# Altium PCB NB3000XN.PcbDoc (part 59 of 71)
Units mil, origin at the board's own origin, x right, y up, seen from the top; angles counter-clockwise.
Board outline 9527.56 x 6929.77 mil, 6 copper layers (Top Layer, GND+SHIELD, MidLayer1, MidLayer2, P2 - 3V3+5V0, Bottom Layer), stack 62.375 mil thick; 832 components, 1027 nets, 4655 pads, 4981 vias.
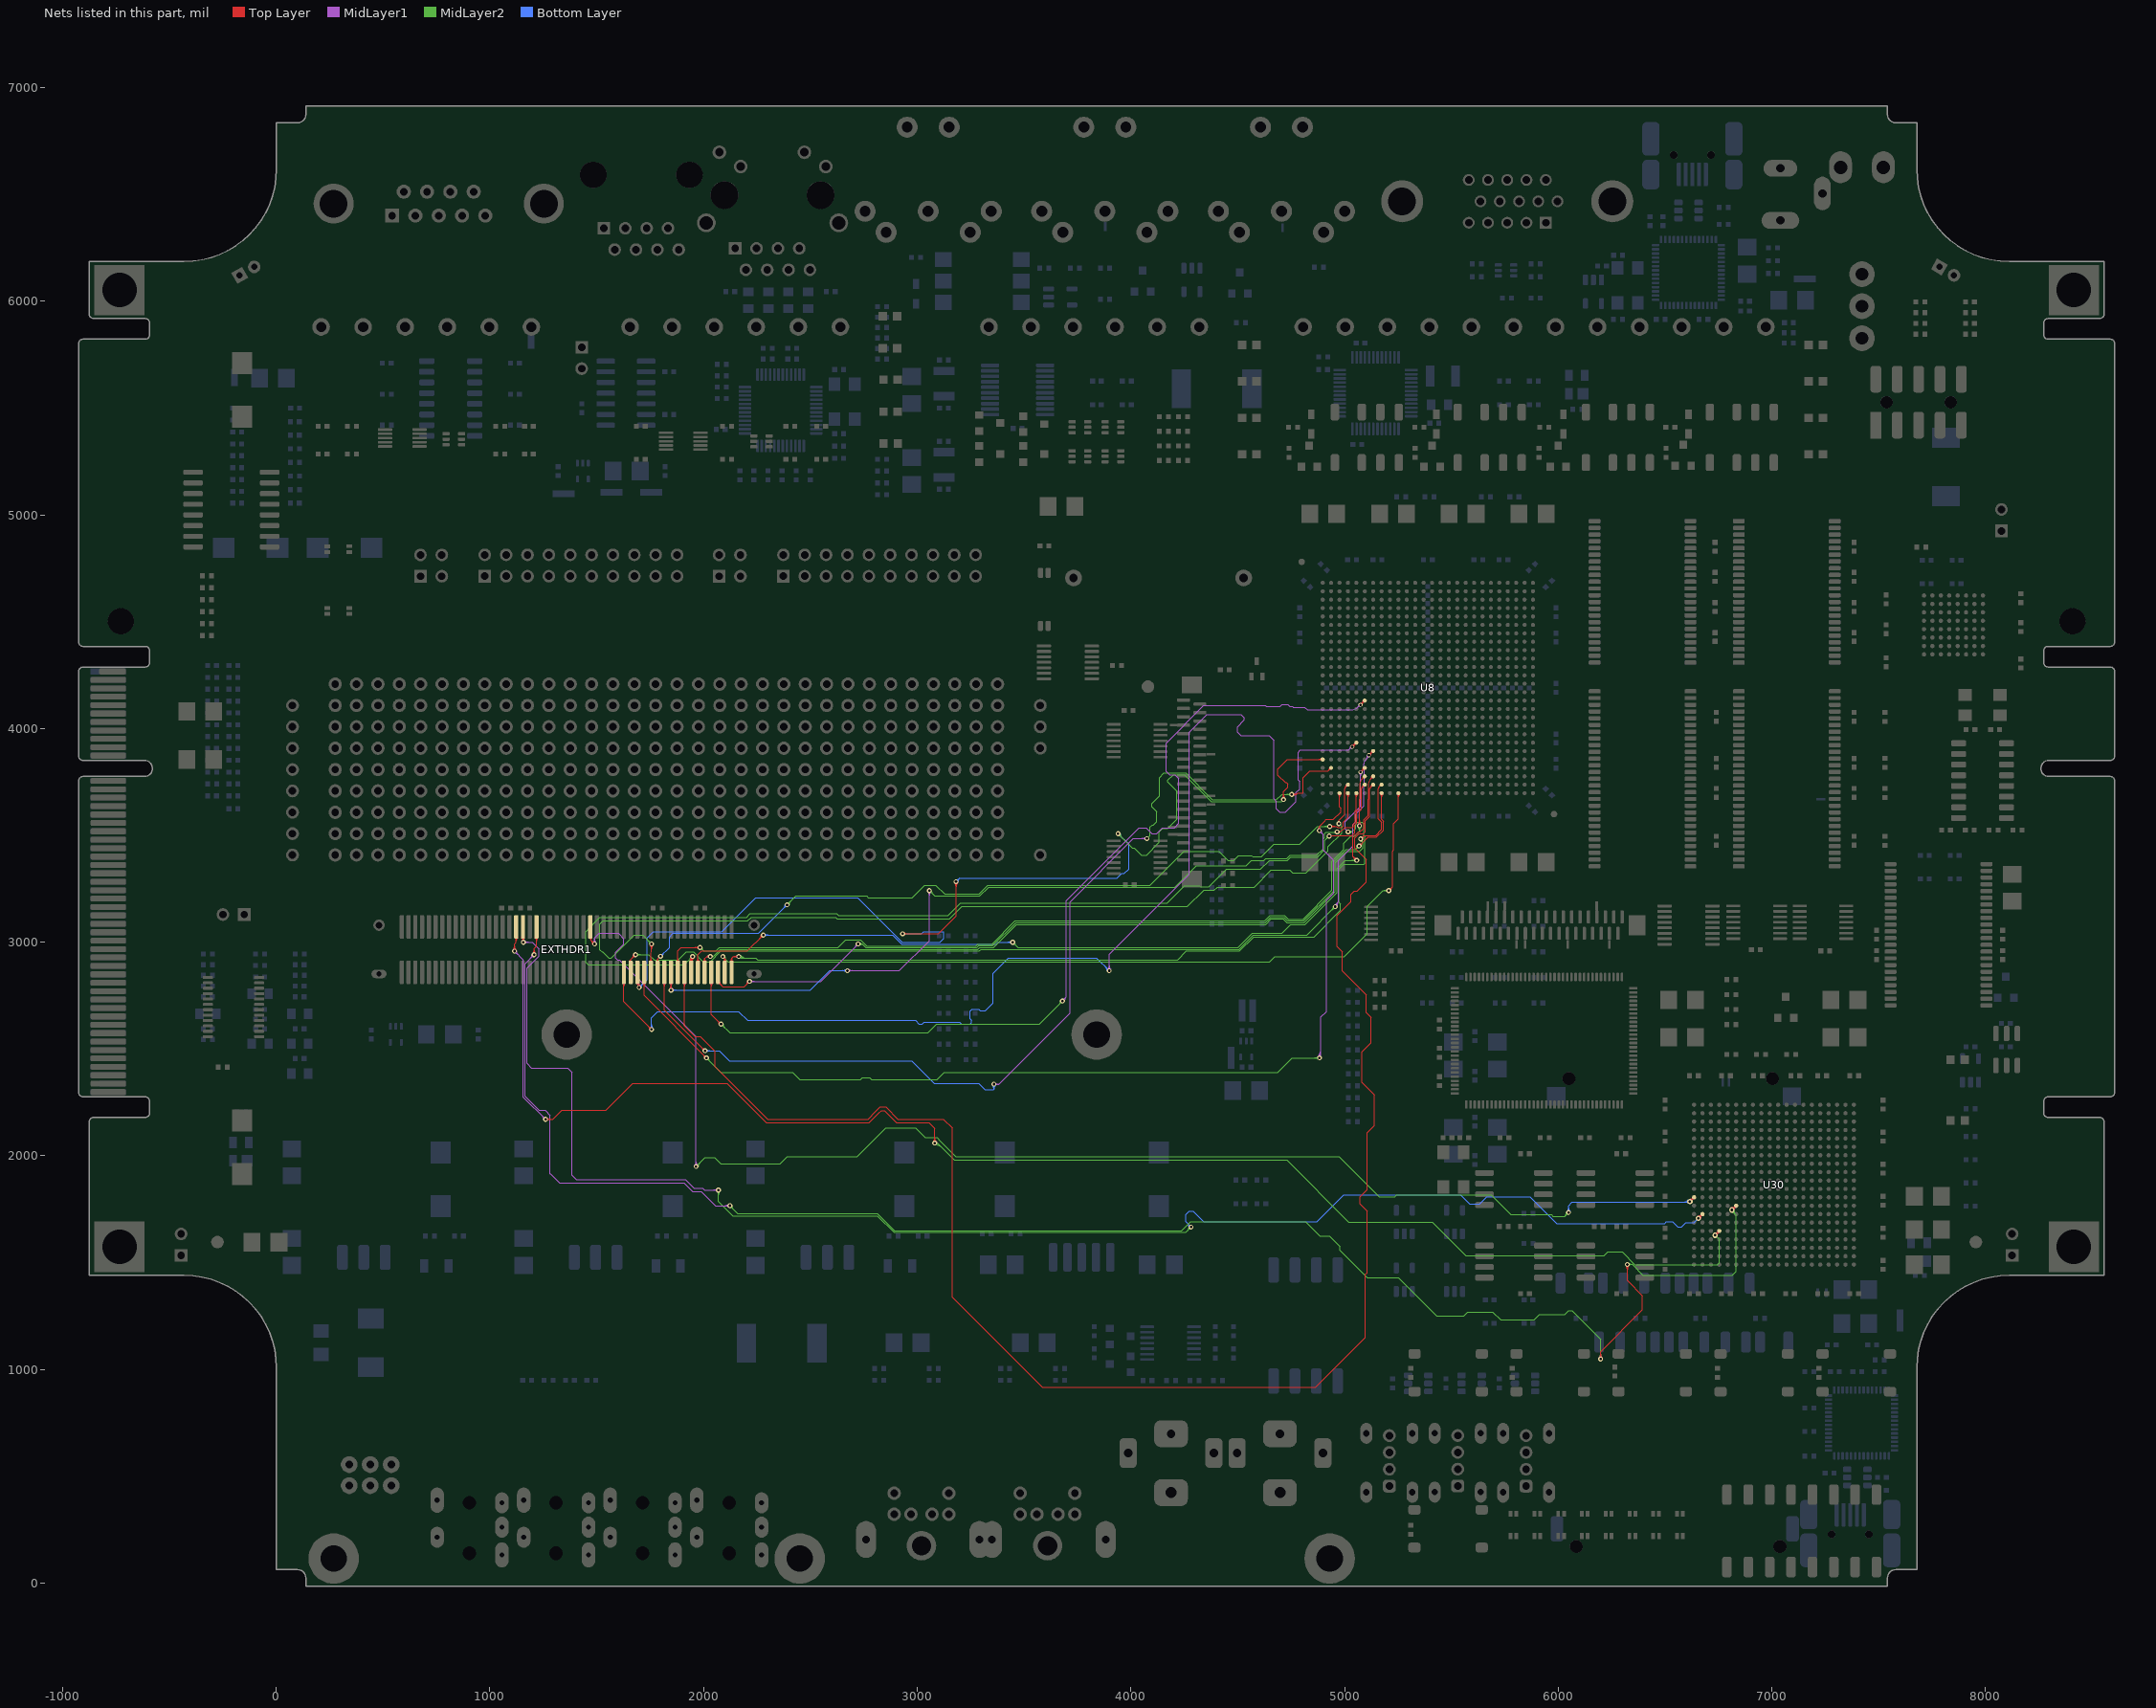
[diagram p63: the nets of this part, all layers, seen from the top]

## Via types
v1: diameter 23, hole 11.81, Top Layer to Bottom Layer, 3672 vias
v2: diameter 26, hole 11.81, Top Layer to Bottom Layer, 461 vias
v3: diameter 19, hole 11.81, Top Layer to Bottom Layer, tented both sides, 396 vias
v4: diameter 23.62, hole 11.81, Top Layer to Bottom Layer, 288 vias
v5: diameter 20, hole 11.81, Top Layer to Bottom Layer, 91 vias
v6: diameter 23, hole 11.81, Top Layer to Bottom Layer, tented both sides, 50 vias
v7: diameter 31, hole 11.81, Top Layer to Bottom Layer, 15 vias
v8: diameter 27.56, hole 11.81, Top Layer to Bottom Layer, tented both sides, 4 vias
v9: diameter 29, hole 11.81, Top Layer to Bottom Layer, 3 vias
v10: diameter 21, hole 11.81, Top Layer to Bottom Layer, 1 vias

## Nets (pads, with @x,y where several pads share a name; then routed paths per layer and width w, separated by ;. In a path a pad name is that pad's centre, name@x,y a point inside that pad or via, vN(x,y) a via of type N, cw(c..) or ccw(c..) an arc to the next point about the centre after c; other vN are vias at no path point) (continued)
PBCTRL.SPARE3: EXTHDR1.43 U30.Y12 | length 7040.8
  Top Layer w4: EXTHDR1.43@1466.36,3019.56 cw(c1460.65,3008.02) 1473.52,3008.02 ; EXTHDR1.43@1468.13,3023.14 cw(c1463.84,3014.46) 1473.52,3014.46 ; EXTHDR1.43@1469.9,3071.85 1469.91,3075.04 1473.52,3075.04 1473.52,3008.37 v1(1490.19,2991.71) ; 1473.52,3016.16 cw(c1480.48,3016.16) EXTHDR1.43@1475.56,3021.07 ; v1@1480.69,2991.71 ccw(c1457.76,2991.71) 1473.97,3007.93 ccw(c1490.19,3024.14) v1@1490.19,3001.21 ; v1@1484.69,2991.71 ccw(c1471.41,2991.71) 1480.8,3001.1 ccw(c1490.19,3010.49) v1@1490.19,2997.21
  Top Layer w8: v2(6616.3,1786.26) U30.Y12@6635.98,1805.94 ; v2@6616.3,1795.26 ccw(c6616.3,1816.99) 6631.66,1801.62 ccw(c6647.03,1786.26) v2@6625.3,1786.26 ; U30.Y12@6630.14,1805.94 cw(c6616.04,1805.94) 6626.01,1795.97 cw(c6635.98,1786) U30.Y12@6635.98,1800.1
  MidLayer1 w4: v1@1483.47,2998.43 ccw(c1467.26,3014.64) 1490.19,3014.64 ccw(c1513.13,3014.64) v1@1496.91,2998.43 ; v1@1486.3,2995.6 ccw(c1476.91,3004.99) 1490.19,3004.99 ccw(c1503.47,3004.99) v1@1494.08,2995.6 ; v1(1490.19,2991.71) 1490.19,3019 1513.19,3042 1600.6,3042 1627.39,3015.22 1627.39,2991.9 1589.19,2953.71 1589.19,2925 1597.48,2916.71 1606.86,2916.71 1965.19,2558.37 v1(1965.19,1950.04) ; v1@1958.47,1956.76 ccw(c1942.26,1972.98) 1965.19,1972.98 ccw(c1988.13,1972.98) v1@1971.91,1956.76 ; v1@1961.3,1953.93 ccw(c1951.91,1963.32) 1965.19,1963.32 ccw(c1978.47,1963.32) v1@1969.08,1953.93
  MidLayer2 w4: v1(1965.19,1950.04) 2006.86,1991.71 2052.02,1991.71 2081.73,1962 2358.27,1962 2393.08,1996.81 2719.94,1996.81 2854.13,2131 2992.56,2131 3038.06,2085.5 3092.42,2085.5 3107.36,2070.56 3181.11,1996.81 4974.77,1996.81 5163.21,1808.37 5235.45,1808.37 5243.78,1816.71 5615.19,1816.71 5687.21,1816.71 5778.88,1725.04 5967.56,1725.04 5975.9,1716.71 6030.19,1716.71 v1(6048.52,1735.04) ; v1@1965.19,1955.54 ccw(c1965.19,1968.82) 1974.58,1959.43 ccw(c1983.97,1950.04) v1@1970.69,1950.04 ; v1@1965.19,1959.54 ccw(c1965.19,1982.48) 1981.41,1966.26 ccw(c1997.63,1950.04) v1@1974.69,1950.04 ; v1@6039.02,1735.04 cw(c6016.09,1735.04) 6032.31,1718.82 cw(c6048.52,1702.61) v1@6048.52,1725.54 ; v1@6043.02,1735.04 cw(c6029.75,1735.04) 6039.13,1725.65 cw(c6048.52,1716.26) v1@6048.52,1729.54
  Bottom Layer w4: v1@6041.81,1741.76 ccw(c6025.59,1757.98) 6048.52,1757.98 ccw(c6071.46,1757.98) v1@6055.24,1741.76 ; v1@6044.64,1738.93 ccw(c6035.25,1748.32) 6048.52,1748.32 ccw(c6061.8,1748.32) v1@6052.41,1738.93 ; v1(6048.52,1735.04) 6048.52,1766.71 6065.19,1783.37 6606.86,1783.37 6615.19,1791.71 6616.3,1791.71 v2(6616.3,1786.26) ; 6582.78,1783.37 ccw(c6582.78,1819.78) v2@6608.52,1794.04 ; 6592.43,1783.37 ccw(c6592.43,1810.12) v2@6611.35,1791.21 ; 6596.71,1783.37 cw(c6596.71,1766.67) v2@6608.52,1778.48 ; 6602.09,1783.37 ccw(c6602.09,1800.47) v2@6614.18,1788.38
PBCTRL.SPARE4: EXTHDR1.65 U30.U16 | length 7661.4
  Top Layer w4: v1@1108.47,2965.09 ccw(c1092.26,2981.31) 1115.19,2981.31 ccw(c1138.13,2981.31) v1@1121.91,2965.09 ; v1@1111.3,2962.26 ccw(c1101.91,2971.65) 1115.19,2971.65 ccw(c1128.47,2971.65) v1@1119.08,2962.26 ; v1(1115.19,2958.37) 1115.19,2990.37 1123.45,2998.63 EXTHDR1.65@1123.45,3071.85 ; EXTHDR1.65@1117.79,3021.07 cw(c1104.13,3007.42) 1123.45,3007.42 cw(c1142.76,3007.42) EXTHDR1.65@1129.1,3021.07 ; v1(1260.86,2171.04) 1294.73,2171.04 1336.69,2213 1543,2213 1669,2339 2111,2339 2128.68,2321.32 2294,2156 2776.25,2156 2822.5,2202.25 2832.75,2212.5 2847.25,2212.5 2903.75,2156 3054,2156 3081.86,2128.14 v1(3081.86,2060) ; v1@1264.75,2167.15 cw(c1274.14,2157.76) 1274.14,2171.04 cw(c1274.14,2184.32) v1@1264.75,2174.93 ; v1@1267.57,2164.32 cw(c1283.79,2148.11) 1283.79,2171.04 cw(c1283.79,2193.98) v1@1267.57,2177.76 ; v1@3075.14,2066.72 ccw(c3058.92,2082.93) 3081.86,2082.93 ccw(c3104.79,2082.93) v1@3088.57,2066.72 ; v1@3077.97,2063.89 ccw(c3068.58,2073.28) 3081.86,2073.28 ccw(c3095.14,2073.28) v1@3085.75,2063.89
  Top Layer w8: v2(6734.41,1628.78) U30.U16@6754.09,1648.46 ; v2@6734.41,1637.78 ccw(c6734.41,1659.51) 6749.77,1644.14 ccw(c6765.14,1628.78) v2@6743.41,1628.78 ; U30.U16@6748.25,1648.46 cw(c6734.15,1648.46) 6744.12,1638.49 cw(c6754.09,1628.52) U30.U16@6754.09,1642.62
  MidLayer1 w4: v1@1115.19,2948.87 cw(c1115.19,2925.94) 1131.41,2942.16 cw(c1147.63,2958.37) v1@1124.69,2958.37 ; v1@1115.19,2952.87 cw(c1115.19,2939.6) 1124.58,2948.99 cw(c1133.97,2958.37) v1@1120.69,2958.37 ; v1(1115.19,2958.37) 1156.86,2916.71 1156.86,2275.04 v1(1260.86,2171.04) ; v1@1251.36,2171.04 ccw(c1228.42,2171.04) 1244.64,2187.26 ccw(c1260.86,2203.48) v1@1260.86,2180.54 ; v1@1255.36,2171.04 ccw(c1242.08,2171.04) 1251.47,2180.43 ccw(c1260.86,2189.82) v1@1260.86,2176.54
  MidLayer2 w4: v1@3081.86,2050.5 cw(c3081.86,1995.13) 3121.01,2034.28 ; v1@3081.86,2054.5 cw(c3081.86,2008.79) 3114.18,2041.11 ; v1@3081.86,2058.5 cw(c3081.86,2022.44) 3107.35,2047.94 ; v1(3081.86,2060) 3095.29,2060 3174.48,1980.81 4729.68,1980.81 5019.78,1690.71 5411.45,1690.71 5568.78,1533.37 6214.19,1533.37 6231.86,1551.04 6299.19,1551.04 6358.86,1491.37 6745.86,1491.37 6754.52,1500.04 6754.52,1608.66 v2(6734.41,1628.78) ; v1@3081.86,2062.5 cw(c3081.86,2036.1) 3100.52,2054.77 ; v1@3081.86,2066.5 cw(c3081.86,2049.76) 3093.7,2061.6
PBCTRL.SPI_CS_N0: EXTHDR1.59 U30.R13 | length 8673.8
  Top Layer w4: v1@1200.14,2948.43 ccw(c1183.92,2964.64) 1206.86,2964.64 ccw(c1229.79,2964.64) v1@1213.57,2948.43 ; v1@1202.97,2945.6 ccw(c1193.58,2954.99) 1206.86,2954.99 ccw(c1220.14,2954.99) v1@1210.75,2945.6 ; v1(1206.86,2941.71) 1206.86,2970 1217.94,2981.08 EXTHDR1.59@1217.94,3071.85 ; EXTHDR1.59@1212.28,3021.07 cw(c1198.62,3007.42) 1217.94,3007.42 cw(c1237.25,3007.42) EXTHDR1.59@1223.59,3021.07 ; v1@6191.81,1055.76 ccw(c6175.59,1071.98) 6198.52,1071.98 ccw(c6221.46,1071.98) v1@6205.24,1055.76 ; v1@6194.64,1052.93 ccw(c6185.25,1062.32) 6198.52,1062.32 ccw(c6211.8,1062.32) v1@6202.41,1052.93 ; v1(6198.52,1049.04) 6198.52,1083.37 6395,1279.85 6395,1345 6323.52,1416.48 v1(6323.52,1491.71) ; v1@6316.81,1484.99 cw(c6300.59,1468.77) 6323.52,1468.77 cw(c6346.46,1468.77) v1@6330.24,1484.99 ; v1@6319.64,1487.82 cw(c6310.25,1478.43) 6323.52,1478.43 cw(c6336.8,1478.43) v1@6327.41,1487.82
  Top Layer w8: v2(6813.15,1746.89) U30.R13@6832.83,1766.57 ; v2@6813.15,1755.89 ccw(c6813.15,1777.62) 6828.51,1762.25 ccw(c6843.88,1746.89) v2@6822.15,1746.89 ; U30.R13@6826.99,1766.57 cw(c6812.89,1766.57) 6822.86,1756.6 cw(c6832.83,1746.63) U30.R13@6832.83,1760.73
  MidLayer1 w4: v1@1197.36,2941.71 cw(c1174.42,2941.71) 1190.64,2925.49 cw(c1206.86,2909.27) v1@1206.86,2932.21 ; v1@1201.36,2941.71 cw(c1188.08,2941.71) 1197.47,2932.32 cw(c1206.86,2922.93) v1@1206.86,2936.21 ; v1(1206.86,2941.71) 1164.86,2899.71 1164.86,2278.35 1230,2213.21 1258.65,2213.21 1281.86,2190 1281.86,1916.71 1283.26,1915.3 1325.57,1873 1908.31,1873 1948.31,1833 1990.02,1833 2056.31,1766.71 v1(2123.52,1766.71) ; v1@2116.81,1759.99 ccw(c2100.59,1743.77) 2100.59,1766.71 ccw(c2100.59,1789.64) v1@2116.81,1773.43 ; v1@2119.64,1762.82 ccw(c2110.25,1753.43) 2110.25,1766.71 ccw(c2110.25,1779.99) v1@2119.64,1770.6
  MidLayer2 w4: v1@2123.52,1757.21 cw(c2123.52,1734.27) 2139.74,1750.49 cw(c2155.96,1766.71) v1@2133.02,1766.71 ; v1@2123.52,1761.21 cw(c2123.52,1747.93) 2132.91,1757.32 cw(c2142.3,1766.71) v1@2129.02,1766.71 ; v1(2123.52,1766.71) 2160.23,1730 2813.69,1730 2893.69,1650 4238.29,1650 4280,1691.71 4818.17,1691.71 4884.84,1625.04 4929.96,1625.04 4979.38,1575.62 4979.38,1557.16 5106.54,1430 5251.9,1430 5270.69,1411.21 5431.86,1250.04 5558.22,1250.04 5577.46,1269.29 5693.57,1269.29 5730.65,1232.21 5888.06,1232.21 5913.06,1257.21 6030.69,1257.21 6048.52,1275.04 6065.19,1275.04 6131.86,1208.37 6198.52,1141.71 v1(6198.52,1049.04) ; v1@6191.81,1055.76 ccw(c6175.59,1071.98) 6198.52,1071.98 ccw(c6221.46,1071.98) v1@6205.24,1055.76 ; v1@6194.64,1052.93 ccw(c6185.25,1062.32) 6198.52,1062.32 ccw(c6211.8,1062.32) v1@6202.41,1052.93 ; v1(6323.52,1491.71) 6347.21,1491.71 6397.21,1441.71 6815.52,1441.71 6832.19,1458.37 6832.19,1722.71 6813.19,1741.71 v2(6813.15,1746.89) ; v1@6327.41,1487.82 cw(c6336.8,1478.43) 6336.8,1491.71 cw(c6336.8,1504.99) v1@6327.41,1495.6 ; v1@6330.24,1484.99 cw(c6346.46,1468.77) 6346.46,1491.71 cw(c6346.46,1514.64) v1@6330.24,1498.43 ; v2@6813.15,1735.89 cw(c6813.15,1721.75) 6823.15,1731.75 ; v2@6820,1745.43 ccw(c6835.95,1742.02) 6824.41,1730.48 ; v2@6823.91,1744.59 ccw(c6844.53,1740.19) 6829.62,1725.28
PBCTRL.SPI_CS_N1: EXTHDR1.63 U30.W14 | length 7615.4
  Top Layer w4: EXTHDR1.63@1149.29,3021.07 cw(c1131.01,3002.8) v1@1156.86,3002.8 ; v1@1150.14,3006.76 ccw(c1133.92,3022.98) 1156.86,3022.98 ccw(c1179.79,3022.98) v1@1163.57,3006.76 ; EXTHDR1.63@1152.12,3023.9 cw(c1140.67,3012.45) 1156.86,3012.45 ; v1@1152.97,3003.93 ccw(c1143.58,3013.32) 1156.86,3013.32 ccw(c1170.14,3013.32) v1@1160.75,3003.93 ; EXTHDR1.63@1154.94,3071.85 1154.94,3075.04 1156.86,3075.04 v1(1156.86,3000.04) ; 1156.86,3012.04 cw(c1169.64,3012.04) EXTHDR1.63@1160.6,3021.07
  Top Layer w8: v2(6655.67,1707.52) U30.W14@6675.35,1727.2 ; v2@6655.67,1716.52 ccw(c6655.67,1738.25) 6671.03,1722.88 ccw(c6686.4,1707.52) v2@6664.67,1707.52 ; U30.W14@6669.51,1727.2 cw(c6655.41,1727.2) 6665.38,1717.23 cw(c6675.35,1707.26) U30.W14@6675.35,1721.36
  MidLayer1 w4: v1(1156.86,3000.04) 1198.52,3000.04 1230,2968.57 1230,2935 1172.86,2877.86 1172.86,2432.14 1195,2410 1365,2410 1385,2390 1385,1908.21 1404.21,1889 1914.94,1889 1954.94,1849 1996.65,1849 2005.65,1840 v1(2070,1840) ; v1@1160.75,2996.15 cw(c1170.14,2986.76) 1170.14,3000.04 cw(c1170.14,3013.32) v1@1160.75,3003.93 ; v1@1163.57,2993.32 cw(c1179.79,2977.11) 1179.79,3000.04 cw(c1179.79,3022.98) v1@1163.57,3006.76 ; v1@2063.28,1833.28 ccw(c2047.06,1817.06) 2047.06,1840 ccw(c2047.06,1862.93) v1@2063.28,1846.72 ; v1@2066.11,1836.11 ccw(c2056.72,1826.72) 2056.72,1840 ccw(c2056.72,1853.28) v1@2066.11,1843.89
  MidLayer2 w4: v1@2063.28,1833.28 cw(c2047.06,1817.06) 2070,1817.06 cw(c2092.93,1817.06) v1@2076.72,1833.28 ; v1@2066.11,1836.11 cw(c2056.72,1826.72) 2070,1826.72 cw(c2083.28,1826.72) v1@2073.89,1836.11 ; v1(2070,1840) 2070,1786.9 2137.81,1719.09 2813.28,1719.09 2890.66,1641.71 4256.86,1641.71 v1(4281.86,1666.71) ; v1@4272.36,1666.71 cw(c4249.42,1666.71) 4265.64,1650.49 cw(c4281.86,1634.27) v1@4281.86,1657.21 ; v1@4276.36,1666.71 cw(c4263.08,1666.71) 4272.47,1657.32 cw(c4281.86,1647.93) v1@4281.86,1661.21
  Bottom Layer w4: v1@4272.36,1666.71 ccw(c4249.42,1666.71) 4265.64,1682.93 ccw(c4281.86,1699.14) v1@4281.86,1676.21 ; v1@4276.36,1666.71 ccw(c4263.08,1666.71) 4272.47,1676.1 ccw(c4281.86,1685.49) v1@4281.86,1672.21 ; v1(4281.86,1666.71) 4256.86,1691.71 4256.86,1725.04 4273.52,1741.71 4290.19,1741.71 4340.19,1691.71 4870.54,1691.71 4995.54,1816.71 5543.33,1816.71 5585,1775.04 5631.86,1775.04 5665.19,1808.37 5867.94,1808.37 5992.94,1683.37 6498.52,1683.37 6506.86,1691.71 6535,1691.71 6560,1666.71 6576.86,1666.71 6598.52,1688.37 6636.52,1688.37 v2(6655.67,1707.52)
PBIO.D0: EXTHDR1.2 U8.AC6 | length 4422.7
  Top Layer w4: EXTHDR1.2@2125.66,2910.03 ccw(c2112.01,2923.68) 2131.32,2923.68 ccw(c2150.64,2923.68) EXTHDR1.2@2136.98,2910.03 ; EXTHDR1.2@2131.32,2859.25 2131.32,2926.32 2138.37,2933.37 v1(2165.19,2933.37) ; v1@2158.47,2926.66 ccw(c2142.26,2910.44) 2142.26,2933.37 ccw(c2142.26,2956.31) v1@2158.47,2940.09 ; v1@2161.3,2929.49 ccw(c2151.91,2920.1) 2151.91,2933.37 ccw(c2151.91,2946.65) v1@2161.3,2937.26 ; v3(5075.04,3796.3) U8.AC6@5094.72,3815.98 ; U8.AC6@5087.22,3815.98 cw(c5069.12,3815.98) 5081.92,3803.18 cw(c5094.72,3790.38) U8.AC6@5094.72,3808.48 ; U8.AC6@5087.38,3815.98 cw(c5069.66,3815.98) 5082.19,3803.45 cw(c5094.72,3790.92) U8.AC6@5094.72,3808.64 ; 5087.84,3809.1 ccw(c5100.65,3796.3) 5082.54,3796.3 cw(c5100.65,3796.3) 5087.84,3809.1 ; 5087.84,3809.1 cw(c5075.04,3821.91) 5075.04,3803.8 ccw(c5075.04,3821.91) 5087.84,3809.1
  MidLayer1 w4: v1(5016.86,3516.71) 5003.86,3529.71 5003.86,3563.71 5064.86,3624.71 5075.04,3634.89 5075.04,3660 5075.04,3670 5075.04,3718.62 v3(5075.04,3796.3) ; v3@5069.85,3791.11 cw(c5057.31,3778.57) 5075.04,3778.57 cw(c5092.77,3778.57) v3@5080.23,3791.11 ; 5075.04,3778.19 cw(c5093.15,3778.19) 5080.34,3791 ccw(c5093.15,3778.19) 5075.04,3778.19 ; 5075.04,3778.19 ccw(c5056.93,3778.19) 5069.74,3791 cw(c5056.93,3778.19) 5075.04,3778.19
  MidLayer2 w4: v1@2163.42,2931.61 ccw(c2179.27,2947.46) 2179.27,2925.04 ; v1(2165.19,2933.37) 2173.52,2925.04 2245,2925.04 2253.67,2916.37 4218.63,2916.37 4260.63,2958.37 4508.86,2958.37 4575.52,3025.04 4857.86,3025.04 4981.86,3149.04 4981.86,3178.14 4973.52,3186.48 ; v1@2166.25,2934.44 ccw(c2188.93,2957.12) 2188.93,2925.04 ; v1@2169.08,2937.26 ccw(c2198.59,2966.77) 2198.59,2925.04 ; v1@2171.91,2940.09 ccw(c2208.25,2976.43) 2208.25,2925.04 ; 4980,3180 4973.52,3186.48 ; v1(5016.86,3516.71) 5034.86,3516.71 ; v1@5024.7,3511.35 cw(c5034.86,3504.41) 5034.86,3516.71 ; v1@5024.7,3522.07 ccw(c5034.86,3529.01) 5034.86,3516.71 ; 4973.52,3186.48 4973.52,3341.71 4997.52,3365.71 5090.19,3365.71 5094.52,3370.04 5094.52,3491.71 5090.19,3496.04 5090.19,3554.37 5081.86,3562.71 5061.19,3562.71 5051.52,3553.04 5051.52,3533.37 5034.86,3516.71
PBIO.D1: EXTHDR1.4 U8.AF10 | length 4178.1
  Top Layer w4: v1(2090.19,2933.37) 2099.83,2923.74 EXTHDR1.4@2099.83,2859.25 ; EXTHDR1.4@2094.17,2910.03 ccw(c2080.51,2923.68) 2099.83,2923.68 ccw(c2119.14,2923.68) EXTHDR1.4@2105.48,2910.03 ; v1(5206.86,3241.71) 5224.19,3259.04 5224.19,3425.5 5230.02,3431.34 5230.02,3555.94 5252.2,3578.12 5252.2,3660 5252.2,3670 U8.AF10@5252.2,3697.87 ; v1@5206.86,3247.21 ccw(c5206.86,3260.49) 5216.25,3251.1 ccw(c5225.64,3241.71) v1@5212.36,3241.71 ; v1@5206.86,3251.21 ccw(c5206.86,3274.14) 5223.07,3257.93 ccw(c5239.29,3241.71) v1@5216.36,3241.71 ; U8.AF10@5246.9,3692.57 cw(c5234.1,3679.77) 5252.2,3679.77 cw(c5270.31,3679.77) U8.AF10@5257.51,3692.57 ; 5252.2,3680.15 cw(c5269.93,3680.15) 5257.4,3692.68 ccw(c5269.93,3680.15) 5252.2,3680.15 ; 5252.2,3680.15 ccw(c5234.48,3680.15) 5247.01,3692.68 cw(c5234.48,3680.15) 5252.2,3680.15
  MidLayer2 w4: v1@2090.19,2923.87 cw(c2090.19,2900.94) 2106.41,2917.16 cw(c2122.63,2933.37) v1@2099.69,2933.37 ; v1@2090.19,2927.87 cw(c2090.19,2914.6) 2099.58,2923.99 cw(c2108.97,2933.37) v1@2095.69,2933.37 ; v1(2090.19,2933.37) 2115.19,2908.37 4648.52,2908.37 4673.52,2933.37 4999.52,2933.37 5106.86,3040.71 5106.86,3168.35 5180.21,3241.71 v1(5206.86,3241.71) ; v1@5200.14,3234.99 ccw(c5183.92,3218.77) 5183.92,3241.71 ccw(c5183.92,3264.64) v1@5200.14,3248.43 ; v1@5202.97,3237.82 ccw(c5193.58,3228.43) 5193.58,3241.71 ccw(c5193.58,3254.99) v1@5202.97,3245.6
PBIO.D2: EXTHDR1.6 U8.AF8 | length 4162.4
  Top Layer w4: EXTHDR1.6@2068.33,2806.13 cw(c2068.33,2788.18) 2081.02,2800.87 ; EXTHDR1.6@2068.33,2859.25 2068.33,2813.57 2090.19,2791.71 2190.19,2791.71 v1(2215.19,2816.71) ; EXTHDR1.6@2072.33,2814.13 ccw(c2083.35,2814.13) EXTHDR1.6@2075.56,2806.34 ; EXTHDR1.6@2076.33,2814.13 ccw(c2097.01,2814.13) 2082.39,2799.51 ; v1@2205.69,2816.71 cw(c2182.76,2816.71) 2198.97,2800.49 cw(c2215.19,2784.27) v1@2215.19,2807.21 ; v1@2209.69,2816.71 cw(c2196.41,2816.71) 2205.8,2807.32 cw(c2215.19,2797.93) v1@2215.19,2811.21 ; v1(5068.52,3450.37) 5109.86,3491.71 5149.21,3491.71 5182.02,3524.52 5182.02,3567.22 5173.46,3575.78 5173.46,3660 5173.46,3670 U8.AF8@5173.46,3697.87 ; v1@5068.52,3455.87 ccw(c5068.52,3469.15) 5077.91,3459.76 ccw(c5087.3,3450.37) v1@5074.02,3450.37 ; v1@5068.52,3459.87 ccw(c5068.52,3482.81) 5084.74,3466.59 ccw(c5100.96,3450.37) v1@5078.02,3450.37 ; U8.AF8@5168.16,3692.57 cw(c5155.36,3679.77) 5173.46,3679.77 cw(c5191.57,3679.77) U8.AF8@5178.77,3692.57 ; U8.AF8@5168.27,3692.68 cw(c5155.74,3680.15) 5173.46,3680.15 cw(c5191.19,3680.15) U8.AF8@5178.66,3692.68
  MidLayer1 w4: v1(2215.19,2816.71) 2548.52,2816.71 v1(2723.52,2991.71) ; v1@2219.08,2812.82 cw(c2228.47,2803.43) 2228.47,2816.71 cw(c2228.47,2829.99) v1@2219.08,2820.6 ; v1@2221.91,2809.99 cw(c2238.13,2793.77) 2238.13,2816.71 cw(c2238.13,2839.64) v1@2221.91,2823.43 ; v1@2714.02,2991.71 cw(c2691.09,2991.71) 2707.31,2975.49 cw(c2723.52,2959.27) v1@2723.52,2982.21 ; v1@2718.02,2991.71 cw(c2704.75,2991.71) 2714.14,2982.32 cw(c2723.52,2972.93) v1@2723.52,2986.21
  MidLayer2 w4: v1(2723.52,2991.71) 2742.71,2991.71 ; v1@2731.08,2985.95 cw(c2742.71,2977.09) 2742.71,2991.71 ; v1@2731.08,2997.47 ccw(c2742.71,3006.32) 2742.71,2991.71 ; v1@5059.02,3450.37 cw(c5036.09,3450.37) 5052.31,3434.16 cw(c5068.52,3417.94) v1@5068.52,3440.87 ; v1@5063.02,3450.37 cw(c5049.75,3450.37) 5059.14,3440.99 cw(c5068.52,3431.6) v1@5068.52,3444.87 ; v1(5068.52,3450.37) 5051.52,3433.37 5006.86,3433.37 4948.86,3375.37 4948.86,3240.35 4808.54,3100.04 4732.86,3100.04 4716.19,3116.71 4654.21,3116.71 4629.21,3091.71 3462.21,3091.71 3353.54,2983.04 3288.04,2983.04 3279.71,2974.71 2759.71,2974.71 2742.71,2991.71
PBIO.D3: EXTHDR1.8 U8.R6 | length 4956.4
  Top Layer w4: EXTHDR1.8@2031.18,2808.48 cw(c2017.52,2794.82) 2036.83,2794.82 cw(c2056.15,2794.82) EXTHDR1.8@2042.49,2808.48 ; EXTHDR1.8@2036.83,2859.25 2036.83,2661.73 v1(2081.86,2616.71) ; v1@2072.36,2616.71 ccw(c2049.42,2616.71) 2065.64,2632.93 ccw(c2081.86,2649.14) v1@2081.86,2626.21 ; v1@2076.36,2616.71 ccw(c2063.08,2616.71) 2072.47,2626.1 ccw(c2081.86,2635.49) v1@2081.86,2622.21 ; v3(5075.04,4111.26) U8.R6@5094.72,4130.94 ; U8.R6@5087.22,4130.94 cw(c5069.12,4130.94) 5081.92,4118.14 cw(c5094.72,4105.34) U8.R6@5094.72,4123.44 ; U8.R6@5087.38,4130.94 cw(c5069.66,4130.94) 5082.19,4118.41 cw(c5094.72,4105.88) U8.R6@5094.72,4123.6 ; 5087.84,4124.06 cw(c5075.04,4136.87) 5075.04,4118.76 ccw(c5075.04,4136.87) 5087.84,4124.06 ; 5087.84,4124.06 ccw(c5100.65,4111.26) 5082.54,4111.26 cw(c5100.65,4111.26) 5087.84,4124.06
  MidLayer1 w4: v1(3680,2725) 3698.52,2743.52 3698.52,3194.69 4038.84,3535 4071.9,3535 4098.52,3508.37 4120.54,3508.37 4148.17,3536 4203.52,3536 4224.19,3556.67 4224.19,3766.39 4206.88,3783.71 4181.48,3783.71 4165,3800.19 4165,3820 ; v1@3680,2730.5 ccw(c3680,2743.78) 3689.39,2734.39 ccw(c3698.78,2725) v1@3685.5,2725 ; v1@3680,2734.5 ccw(c3680,2757.43) 3696.22,2741.22 ccw(c3712.43,2725) v1@3689.5,2725 ; 4165.19,3820 4165.19,3932.43 4340.47,4107.71 4630.15,4107.71 4634.15,4103.71 4699.08,4103.71 4707.29,4111.92 4735.3,4111.92 4743.51,4103.71 4756.15,4103.71 4759.82,4100.04 4812.82,4100.04 4825.46,4087.4 4860,4087.4 4870,4087.4 4918.62,4087.4 4938.04,4087.4 5012.16,4087.4 ; 4998.23,4087.4 5012.16,4087.4 ; v3@5067.57,4111.91 cw(c5049.53,4113.49) 5061.17,4099.62 ; v3@5074.39,4103.79 ccw(c5072.81,4085.75) 5061.17,4099.62 ; 5012.16,4087.4 5031.66,4087.4 ccw(c5031.66,4129.13) 5061.17,4099.62
  MidLayer2 w4: v1@2081.86,2607.21 cw(c2081.86,2584.27) 2098.07,2600.49 cw(c2114.29,2616.71) v1@2091.36,2616.71 ; v1@2081.86,2611.21 cw(c2081.86,2597.93) 2091.25,2607.32 cw(c2100.64,2616.71) v1@2087.36,2616.71 ; v1(2081.86,2616.71) 2122.56,2576 3049.65,2576 3090.35,2616.71 3559.84,2616.71 3571.71,2616.71 v1(3680,2725) ; v1@3670.5,2725 cw(c3647.56,2725) 3663.78,2708.78 cw(c3680,2692.56) v1@3680,2715.5 ; v1@3674.5,2725 cw(c3661.22,2725) 3670.61,2715.61 cw(c3680,2706.22) v1@3680,2719.5
PBIO.D4: EXTHDR1.10 U8.AE8 | length 4038.7
  Top Layer w4: EXTHDR1.10@1999.72,2910.06 ccw(c1986.41,2923.52) 2005.34,2923.52 ; EXTHDR1.10@2005.34,2904.36 EXTHDR1.10@2005.34,2859.25 2005.34,2923.52 ; EXTHDR1.10@2010.96,2910.06 cw(c2024.27,2923.52) 2005.34,2923.52 ; v1@2023.68,2928.53 ccw(c2015.19,2923.51) 2015.19,2933.37 ; v1@2023.68,2938.22 cw(c2015.19,2943.24) 2015.19,2933.37 ; v1(2031.86,2933.37) 2015.19,2933.37 ; v1(5075.52,3483.37) 5092.19,3500.04 5146.23,3500.04 5174.02,3527.84 5174.02,3561.21 5168.52,3566.71 5165.19,3570.04 5157.96,3577.27 5157.96,3660 5157.96,3670 5157.96,3717.53 cw(c5168.11,3717.53) 5160.93,3724.71 ; v1@5075.52,3488.87 ccw(c5075.52,3502.15) 5084.91,3492.76 ccw(c5094.3,3483.37) v1@5081.02,3483.37 ; v1@5075.52,3492.87 ccw(c5075.52,3515.81) 5091.74,3499.59 ccw(c5107.96,3483.37) v1@5085.02,3483.37 ; U8.AE8@5166.12,3737.24 cw(c5148.4,3737.24) 5160.93,3724.71 ; U8.AE8@5173.46,3729.9 ccw(c5173.46,3712.17) 5160.93,3724.71 ; 2005.34,2923.52 2015.19,2933.37 ; 2005.34,2923.52 2015.19,2933.37
  MidLayer2 w4: v1(2031.86,2933.37) 2045.19,2933.37 2078.52,2966.71 2960,2966.71 3048.52,2966.71 3283.29,2966.71 3291.63,2975.04 3356.86,2975.04 3465.19,3083.37 4632.19,3083.37 4657.19,3108.37 4712.52,3108.37 4729.19,3091.71 4811.52,3091.71 4956.86,3237.04 4956.86,3372.06 5009.84,3425.04 5040,3425.04 5069.86,3425.04 5086.52,3441.71 5086.52,3466.71 5075.52,3477.71 v1(5075.52,3483.37) ; v1@5075.52,3473.87 cw(c5075.52,3464.62) 5082.07,3471.16 ; v1@5079.92,3480.07 ccw(c5084.36,3476.73) 5080.43,3472.8 ; v1@5083.12,3477.67 ccw(c5088.08,3473.93) 5083.69,3469.54
PBIO.D5: EXTHDR1.12 U8.AD7 | length 4431.8
  Top Layer w4: EXTHDR1.12@1968.19,2910.03 ccw(c1954.53,2923.68) 1973.84,2923.68 ccw(c1993.16,2923.68) EXTHDR1.12@1979.5,2910.03 ; EXTHDR1.12@1973.84,2859.25 1973.84,2941.69 1990.52,2958.37 2204.52,2958.37 v1(2279.52,3033.37) ; v1@2270.02,3033.37 cw(c2247.09,3033.37) 2263.31,3017.16 cw(c2279.52,3000.94) v1@2279.52,3023.87 ; v1@2274.02,3033.37 cw(c2260.75,3033.37) 2270.14,3023.99 cw(c2279.52,3014.6) v1@2279.52,3027.87 ; v1@5047.36,3383.37 ccw(c5024.42,3383.37) 5040.64,3399.59 ccw(c5056.86,3415.81) v1@5056.86,3392.87 ; v1@5051.36,3383.37 ccw(c5038.08,3383.37) 5047.47,3392.76 ccw(c5056.86,3402.15) v1@5056.86,3388.87 ; v1(5056.86,3383.37) 5040.19,3400.04 5040.19,3491.71 5065.19,3516.71 5073.52,3516.71 5090.19,3533.37 5090.19,3573.71 5110.23,3593.75 5110.23,3660 5110.23,3670 5110.23,3736.73 ; 5110.23,3736.73 cw(c5148.91,3736.73) 5121.56,3764.08 ; 5110.23,3736.73 cw(c5148.91,3736.73) 5121.56,3764.08 ; 5121.56,3764.08 ccw(c5109.03,3776.61) 5126.75,3776.61 cw(c5109.03,3776.61) 5121.56,3764.08 ; 5121.56,3764.08 cw(c5134.09,3751.55) 5134.09,3769.27 ccw(c5134.09,3751.55) 5121.56,3764.08
  MidLayer2 w4: 3463.52,2983.37 v1(3446.86,3000.04) 3472.19,2974.71 4502.56,2974.71 4569.56,3041.71 4706.86,3041.71 4748.52,3083.37 4815.19,3083.37 4965.19,3233.37 4965.19,3344.71 5003.86,3383.37 v1(5056.86,3383.37) ; v1@5050.14,3376.66 ccw(c5033.92,3360.44) 5033.92,3383.37 ccw(c5033.92,3406.31) v1@5050.14,3390.09 ; v1@5052.97,3379.49 ccw(c5043.58,3370.1) 5043.58,3383.37 ccw(c5043.58,3396.65) v1@5052.97,3387.26 ; 3456.25,2990.65 cw(c3465.64,3000.04) 3452.36,3000.04 ccw(c3465.64,3000.04) 3456.25,2990.65 ; 3456.25,2990.65 ccw(c3446.86,2981.26) 3446.86,2994.54 cw(c3446.86,2981.26) 3456.25,2990.65 ; 3463.07,2983.82 cw(c3479.29,3000.04) 3456.36,3000.04 ccw(c3479.29,3000.04) 3463.08,2983.82 ; 3463.07,2983.82 ccw(c3446.86,2967.61) 3446.86,2990.54 cw(c3446.86,2967.61) 3463.08,2983.82
  Bottom Layer w4: v1(2279.52,3033.37) 2825,3033.37 2840.19,3033.37 2885.71,3033.37 2927.37,2991.71 2940,2991.71 3370,2991.71 3378.33,3000.04 v1(3446.86,3000.04) ; v1@2283.41,3029.49 cw(c2292.8,3020.1) 2292.8,3033.37 cw(c2292.8,3046.65) v1@2283.41,3037.26 ; v1@2286.24,3026.66 cw(c2302.46,3010.44) 2302.46,3033.37 cw(c2302.46,3056.31) v1@2286.24,3040.09 ; v1@3440.14,2993.32 ccw(c3423.92,2977.11) 3423.92,3000.04 ccw(c3423.92,3022.98) v1@3440.14,3006.76 ; v1@3442.97,2996.15 ccw(c3433.58,2986.76) 3433.58,3000.04 ccw(c3433.58,3013.32) v1@3442.97,3003.93
PBIO.D6: EXTHDR1.14 U8.AD6 | length 5166.2
  Top Layer w4: EXTHDR1.14@1936.69,2910.03 ccw(c1928.24,2918.48) 1940.19,2918.48 ; EXTHDR1.14@1940.19,2883.37 1940.19,2925.04 ; EXTHDR1.14@1940.19,2890.32 cw(c1991.58,2890.32) v1@1955.24,2926.66 ; EXTHDR1.14@1940.19,2899.98 cw(c1981.92,2899.98) v1@1952.41,2929.49 ; EXTHDR1.14@1940.19,2909.63 cw(c1972.27,2909.63) v1@1949.58,2932.31 ; 1940.19,2916.9 ccw(c1952.02,2916.9) EXTHDR1.14@1944.79,2907.53 ; 1940.19,2919.29 cw(c1962.61,2919.29) v1@1946.76,2935.14 ; EXTHDR1.14@1947.24,2910.7 cw(c1958.31,2925.04) 1940.19,2925.04 ; v1(1948.52,2933.37) 1940.19,2925.04 ; v1(4928.52,3496.71) 4931.86,3493.37 4935.19,3493.37 4940.19,3498.37 5035.54,3498.37 5049.19,3512.02 5049.19,3538 5049.19,3548.79 5058,3557.6 5058,3559.52 5058,3574 5058,3612.5 5070.86,3625.36 5070.86,3660 5070.86,3670 5070.86,3736.73 ; 5070.86,3736.73 cw(c5109.54,3736.73) 5082.19,3764.08 ; 5070.86,3736.73 cw(c5109.54,3736.73) 5082.19,3764.08 ; 5082.19,3764.08 ccw(c5069.66,3776.61) 5087.38,3776.61 cw(c5069.66,3776.61) 5082.19,3764.08 ; 5082.19,3764.08 cw(c5094.72,3751.55) 5094.72,3769.27 ccw(c5094.72,3751.55) 5082.19,3764.08
  MidLayer2 w4: v1@1939.02,2933.37 cw(c1916.09,2933.37) 1932.31,2917.16 cw(c1948.52,2900.94) v1@1948.52,2923.87 ; v1@1943.02,2933.37 cw(c1929.75,2933.37) 1939.14,2923.99 cw(c1948.52,2914.6) v1@1948.52,2927.87 ; v1(1948.52,2933.37) 1909.15,2894 1461,2894 1448.52,2906.48 1448.52,3050.04 1515.19,3116.71 2200.9,3116.71 2217.56,3133.37 2623.52,3133.37 2631.86,3125.04 3145.54,3125.04 3203.88,3183.37 4169.82,3183.37 4251.44,3265 4280.15,3265 4321.21,3265 4326.84,3259.37 4365.19,3259.37 4447.52,3341.71 4606.86,3341.71 4648.52,3383.37 4732.86,3383.37 4748.52,3399.04 4873.19,3399.04 4907.52,3433.37 4907.52,3475.71 v1(4928.52,3496.71) ; v1@4919.02,3496.71 cw(c4896.09,3496.71) 4912.31,3480.49 cw(c4928.52,3464.27) v1@4928.52,3487.21 ; v1@4923.02,3496.71 cw(c4909.75,3496.71) 4919.14,3487.32 cw(c4928.52,3477.93) v1@4928.52,3491.21
PBIO.D7: EXTHDR1.16 U8.AE7 | length 8412.2
  Top Layer w4: EXTHDR1.16@1905.19,2808.48 cw(c1891.54,2794.82) 1910.85,2794.82 cw(c1930.16,2794.82) EXTHDR1.16@1916.51,2808.48 ; EXTHDR1.16@1910.85,2859.25 1910.85,2608.37 1960.85,2558.37 1985,2558.37 2054.4,2488.97 2054.4,2418.22 2300.63,2172 2345,2172 2769.62,2172 2806.5,2208.88 2826.12,2228.5 2853.88,2228.5 2910.38,2172 3123,2172 3165.19,2129.81 3165.19,1337.04 ; 3165.19,1990 3165.19,1337.04 ; 3165.19,1337.04 3585.86,916.37 4864.86,916.37 5098.52,1150.04 5098.52,1444.69 5106.86,1453.02 5106.86,1741.71 5073.52,1775.04 5073.52,1808.37 5106.86,1841.71 5106.86,2108.37 5140,2141.52 5140,2285.94 5082.02,2343.91 5082.02,2487.02 5123.69,2528.69 5123.69,2648.95 5102.5,2670.14 5102.5,2753.48 5088.77,2767.21 5088.67,2767.21 4990.19,2865.68 4990.19,2955.04 4965.19,2980.04 4965.19,3125.04 5031.19,3191.04 5031.19,3224.37 ; 5031.19,3224.37 5045.52,3238.71 ; 5031.19,3224.37 5045.52,3238.71 ; 5045.52,3238.71 5059.21,3238.71 5102.86,3282.35 5102.86,3287.71 5102.86,3300 5102.86,3387.37 5048.52,3441.71 5048.52,3488.73 5068.17,3508.37 5089.19,3508.37 5098.52,3517.71 5098.52,3569.37 5118.59,3589.44 5118.59,3655.26 5118.59,3660 5118.59,3670 5118.59,3717.53 ; 5118.59,3717.53 cw(c5128.74,3717.53) 5121.56,3724.71 ; 5118.59,3717.53 cw(c5128.74,3717.53) 5121.56,3724.71 ; 5121.56,3724.71 cw(c5134.09,3712.17) 5134.09,3729.9 ccw(c5134.09,3712.17) 5121.56,3724.71 ; 5121.56,3724.71 ccw(c5109.03,3737.24) 5126.75,3737.24 cw(c5109.03,3737.24) 5121.56,3724.71
PBIO.D8: EXTHDR1.18 U8.AE6 | length 4204
  Top Layer w4: EXTHDR1.18@1873.7,2910.03 ccw(c1860.04,2923.68) 1879.35,2923.68 ccw(c1898.67,2923.68) EXTHDR1.18@1885.01,2910.03 ; EXTHDR1.18@1879.35,2859.25 1879.35,2958.37 1896.02,2975.04 v1(1983.52,2975.04) ; v1@1976.81,2968.32 ccw(c1960.59,2952.11) 1960.59,2975.04 ccw(c1960.59,2997.98) v1@1976.81,2981.76 ; v1@1979.64,2971.15 ccw(c1970.25,2961.76) 1970.25,2975.04 ccw(c1970.25,2988.32) v1@1979.64,2978.93 ; v1@5063.47,3551.76 ccw(c5047.26,3567.98) 5070.19,3567.98 ccw(c5093.13,3567.98) v1@5076.91,3551.76 ; v1@5066.3,3548.93 ccw(c5056.91,3558.32) 5070.19,3558.32 ccw(c5083.47,3558.32) v1@5074.08,3548.93 ; v1(5070.19,3545.04) 5070.19,3613.37 5079.22,3622.4 5079.22,3655.26 5079.22,3660 5079.22,3670 5079.22,3717.53 ; 5079.22,3717.53 cw(c5089.37,3717.53) 5082.19,3724.71 ; 5079.22,3717.53 cw(c5089.37,3717.53) 5082.19,3724.71 ; 5082.19,3724.71 cw(c5094.72,3712.17) 5094.72,3729.9 ccw(c5094.72,3712.17) 5082.19,3724.71 ; 5082.19,3724.71 ccw(c5069.66,3737.24) 5087.38,3737.24 cw(c5069.66,3737.24) 5082.19,3724.71
  MidLayer2 w4: v1@1983.52,2965.54 cw(c1983.52,2942.61) 1999.74,2958.82 cw(c2015.96,2975.04) v1@1993.02,2975.04 ; v1@1983.52,2969.54 cw(c1983.52,2956.26) 1992.91,2965.65 cw(c2002.3,2975.04) v1@1989.02,2975.04 ; v1(1983.52,2975.04) 2000.19,2958.37 2057.86,2958.37 2074.52,2975.04 2630.04,2975.04 2665,3010 2735.73,3010 2763.02,2982.71 3274.33,2982.71 3282.67,2991.04 3350.23,2991.04 3459.23,3100.04 4626.23,3100.04 4651.19,3125 4719.13,3125 4719.17,3125.04 4736.17,3108.04 4805.23,3108.04 4940.86,3243.67 4940.86,3295 ; 4940.86,3299.37 4940.86,3295 ; v1@5063.47,3538.32 cw(c5047.26,3522.11) 5070.19,3522.11 cw(c5093.13,3522.11) v1@5076.91,3538.32 ; v1@5066.3,3541.15 cw(c5056.91,3531.76) 5070.19,3531.76 cw(c5083.47,3531.76) v1@5074.08,3541.15 ; v1(5070.19,3545.04) 5070.19,3520.19 5047.2,3497.2 5030.68,3497.2 4996.86,3463.37 4996.86,3434.69 4940.86,3378.69 4940.86,3295
PBIO.D9: EXTHDR1.20 U8.AF5 | length 4401.1
  Top Layer w4: v1@1841.14,2781.76 ccw(c1824.92,2797.98) 1847.86,2797.98 ccw(c1870.79,2797.98) v1@1854.57,2781.76 ; EXTHDR1.20@1842.2,2808.48 cw(c1828.55,2794.82) 1847.86,2794.82 cw(c1867.17,2794.82) EXTHDR1.20@1853.51,2808.48 ; v1@1843.97,2778.93 ccw(c1834.58,2788.32) 1847.86,2788.32 ccw(c1861.14,2788.32) v1@1851.75,2778.93 ; v1(1847.86,2775.04) 1847.86,2814.13 EXTHDR1.20@1847.86,2859.25 ; v1(4965.19,3516.71) 4981.86,3516.71 ; v1@4973.36,3511.87 cw(c4981.86,3506.84) 4981.86,3516.71 ; v1@4973.36,3521.55 ccw(c4981.86,3526.58) 4981.86,3516.71 ; U8.AF5@5050.05,3692.57 cw(c5037.25,3679.77) 5055.35,3679.77 cw(c5073.46,3679.77) U8.AF5@5060.66,3692.57 ; U8.AF5@5050.16,3692.68 cw(c5037.63,3680.15) 5055.35,3680.15 cw(c5073.08,3680.15) U8.AF5@5060.55,3692.68 ; U8.AF5@5055.35,3697.87 5055.35,3670 5055.35,3660 5055.35,3621.17 5050,3615.81 5050,3560.92 5041,3551.92 5041,3542 5036.37,3537.37 5002.52,3537.37 4981.86,3516.71
  MidLayer1 w4: v1(2673.52,2866.71) 2916.95,2866.71 3056.86,3006.61 v1(3056.86,3241.71) ; v1@2677.41,2862.82 cw(c2686.8,2853.43) 2686.8,2866.71 cw(c2686.8,2879.99) v1@2677.41,2870.6 ; v1@2680.24,2859.99 cw(c2696.46,2843.77) 2696.46,2866.71 cw(c2696.46,2889.64) v1@2680.24,2873.43 ; v1@3050.14,3234.99 cw(c3033.92,3218.77) 3056.86,3218.77 cw(c3079.79,3218.77) v1@3063.57,3234.99 ; v1@3052.97,3237.82 cw(c3043.58,3228.43) 3056.86,3228.43 cw(c3070.14,3228.43) v1@3060.75,3237.82
  MidLayer2 w4: v1@3056.86,3232.21 cw(c3056.86,3209.27) 3073.07,3225.49 cw(c3089.29,3241.71) v1@3066.36,3241.71 ; v1@3056.86,3236.21 cw(c3056.86,3222.93) 3066.25,3232.32 cw(c3075.64,3241.71) v1@3062.36,3241.71 ; v1(3056.86,3241.71) 3081.52,3217.04 3292.84,3217.04 3334.17,3258.37 4206.86,3258.37 4306.86,3358.37 4540.19,3358.37 4565.19,3383.37 4623.52,3383.37 4631.86,3391.71 4729.88,3391.71 4745.21,3407.04 4869.88,3407.04 4899.52,3436.69 4899.52,3483.37 4906.86,3490.71 4906.86,3508.37 4912.86,3514.37 4956.86,3514.37 4959.19,3516.71 v1(4965.19,3516.71)
  Bottom Layer w4: v1(1847.86,2775.04) 2500.19,2775.04 2591.86,2866.71 v1(2673.52,2866.71) ; v1@1851.75,2771.15 cw(c1861.14,2761.76) 1861.14,2775.04 cw(c1861.14,2788.32) v1@1851.75,2778.93 ; v1@1854.57,2768.32 cw(c1870.79,2752.11) 1870.79,2775.04 cw(c1870.79,2797.98) v1@1854.57,2781.76 ; v1@2666.81,2859.99 ccw(c2650.59,2843.77) 2650.59,2866.71 ccw(c2650.59,2889.64) v1@2666.81,2873.43 ; v1@2669.64,2862.82 ccw(c2660.25,2853.43) 2660.25,2866.71 ccw(c2660.25,2879.99) v1@2669.64,2870.6
PBIO.D10: EXTHDR1.22 U8.AC2 | length 5268.3
  Top Layer w4: EXTHDR1.22@1810.7,2808.48 cw(c1797.05,2794.82) 1816.36,2794.82 cw(c1835.67,2794.82) EXTHDR1.22@1822.02,2808.48 ; EXTHDR1.22@1816.36,2859.25 1816.36,2682.2 v1(2006.86,2491.71) ; v1@1997.36,2491.71 ccw(c1974.42,2491.71) 1990.64,2507.93 ccw(c2006.86,2524.14) v1@2006.86,2501.21 ; v1@2001.36,2491.71 ccw(c1988.08,2491.71) 1997.47,2501.1 ccw(c2006.86,2510.49) v1@2006.86,2497.21 ; v1(4753.19,3691.71) 4775.39,3691.71 ; v1@4759.19,3691.71 4775.39,3691.71 ; 4766.04,3691.71 cw(c4766.04,3703.98) 4757.17,3695.51 ccw(c4766.04,3703.98) 4766.04,3691.71 ; 4766.04,3691.71 ccw(c4766.04,3679.44) 4757.17,3687.91 cw(c4766.04,3679.44) 4766.04,3691.71 ; 4775.39,3691.71 cw(c4775.39,3712.9) 4760.06,3698.27 ccw(c4775.39,3712.9) 4775.39,3691.71 ; 4775.39,3691.71 ccw(c4775.39,3670.51) 4760.06,3685.15 cw(c4775.39,3670.51) 4775.39,3691.71 ; 4775.39,3691.71 4782.73,3699.04 4805.25,3699.04 4806.86,3700.65 4806.86,3769.29 4838.04,3800.48 4860,3800.48 4870,3800.48 4917.53,3800.48 ; 4917.53,3800.48 ccw(c4917.53,3810.63) 4924.71,3803.45 ; 4917.53,3800.48 ccw(c4917.53,3810.63) 4924.71,3803.45 ; 4924.71,3803.45 ccw(c4912.17,3815.98) 4929.9,3815.98 cw(c4912.17,3815.98) 4924.71,3803.45 ; 4924.71,3803.45 cw(c4937.24,3790.92) 4937.24,3808.64 ccw(c4937.24,3790.92) 4924.71,3803.45
  MidLayer1 w4: v1(3359.19,2335.71) 3381.21,2335.71 ; v1@3363.19,2331.93 cw(c3371.94,2323.68) 3371.94,2335.71 cw(c3371.94,2347.73) v1@3363.19,2339.48 ; v1@3366.1,2329.19 cw(c3381.21,2314.94) 3381.21,2335.71 ; v1@3366.1,2342.23 ccw(c3381.21,2356.48) 3381.21,2335.71 ; v1@4068.47,3478.32 ccw(c4052.26,3462.11) 4052.26,3485.04 ccw(c4052.26,3507.98) v1@4068.47,3491.76 ; v1@4071.3,3481.15 ccw(c4061.91,3471.76) 4061.91,3485.04 ccw(c4061.91,3498.32) v1@4071.3,3488.93 ; v1@4073.52,3483.37 v1(4075.19,3485.04) 4011.5,3485.04 3714.86,3188.39 3714.86,2691.37 3714.86,2669.35 3381.21,2335.71
  MidLayer2 w4: v1(4075.19,3485.04) 4089.36,3499.21 4089.36,3538.62 4099.94,3549.21 4105.77,3549.21 4120,3563.43 4120,3612.15 4097.69,3634.46 4097.69,3648.96 4134.24,3685.51 4134.24,3770.76 ; v1@4746.47,3684.99 ccw(c4730.26,3668.77) 4730.26,3691.71 ccw(c4730.26,3714.64) v1@4746.47,3698.43 ; v1@4749.3,3687.82 ccw(c4739.91,3678.43) 4739.91,3691.71 ccw(c4739.91,3704.99) v1@4749.3,3695.6 ; v1(4753.19,3691.71) 4706.86,3691.71 4681.86,3666.71 4381.86,3666.71 4256.86,3791.71 4155.19,3791.71 ; 4134.24,3770.76 4155.19,3791.71 ; 4134.24,3770.76 4155.19,3791.71
  Bottom Layer w4: v1(2006.86,2491.71) 2075,2491.71 2121.71,2445 2773.29,2445 2973.37,2445 2994.43,2423.95 3078.87,2339.5 3288.65,2339.5 3317.65,2310.5 3358,2310.5 3359.19,2311.69 v1(3359.19,2335.71) v1@3353.08,2335.71 ; v1@2010.75,2487.82 cw(c2020.14,2478.43) 2020.14,2491.71 cw(c2020.14,2504.99) v1@2010.75,2495.6 ; v1@2013.57,2484.99 cw(c2029.79,2468.77) 2029.79,2491.71 cw(c2029.79,2514.64) v1@2013.57,2498.43 ; v1@3352.47,2328.99 cw(c3336.26,2312.77) 3359.19,2312.77 cw(c3382.13,2312.77) v1@3365.91,2328.99 ; v1@3355.3,2331.82 cw(c3345.91,2322.43) 3359.19,2322.43 cw(c3372.47,2322.43) v1@3363.08,2331.82
PBIO.D11: EXTHDR1.24 U8.AF4 | length 4168.6
  Top Layer w4: EXTHDR1.24@1780.06,2910.77 ccw(c1772.84,2920.38) 1784.87,2920.38 ; EXTHDR1.24@1784.87,2859.25 1784.87,2920.38 ; EXTHDR1.24@1789.67,2910.76 cw(c1796.89,2920.38) 1784.87,2920.38 ; v1(1798.52,2934.04) 1784.87,2920.38 ; v1(4930.86,3541.71) 4962.59,3541.71 4967.93,3536.37 4986.52,3536.37 4994.19,3544.04 4994.19,3562.91 5015.98,3584.71 5015.98,3660 5015.98,3670 U8.AF4@5015.98,3697.87 ; v1@4934.75,3537.82 cw(c4944.14,3528.43) 4944.14,3541.71 cw(c4944.14,3554.99) v1@4934.75,3545.6 ; v1@4937.57,3534.99 cw(c4953.79,3518.77) 4953.79,3541.71 cw(c4953.79,3564.64) v1@4937.57,3548.43 ; U8.AF4@5010.68,3692.57 cw(c4997.88,3679.77) 5015.98,3679.77 cw(c5034.09,3679.77) U8.AF4@5021.29,3692.57 ; U8.AF4@5010.79,3692.68 cw(c4998.26,3680.15) 5015.98,3680.15 cw(c5033.71,3680.15) U8.AF4@5021.18,3692.68
  MidLayer2 w4: v1(2390.86,3175.04) 2433.19,3217.37 2763.02,3217.37 2771.69,3208.71 2976.84,3208.71 3035.17,3267.04 3086.88,3267.04 3128.88,3225.04 3289.52,3225.04 3331.19,3266.71 4090.19,3266.71 4248.52,3425.04 4412.19,3425.04 4453.86,3383.37 4482.52,3383.37 4504.19,3405.04 4565.19,3405.04 4570.19,3400.04 4612.21,3400.04 4670.54,3458.37 4790.52,3458.37 4873.86,3541.71 v1(4930.86,3541.71) ; v1@2390.86,3180.54 ccw(c2390.86,3193.82) 2400.25,3184.43 ccw(c2409.64,3175.04) v1@2396.36,3175.04 ; v1@2390.86,3184.54 ccw(c2390.86,3207.48) 2407.07,3191.26 ccw(c2423.29,3175.04) v1@2400.36,3175.04 ; v1@4924.14,3534.99 ccw(c4907.92,3518.77) 4907.92,3541.71 ccw(c4907.92,3564.64) v1@4924.14,3548.43 ; v1@4926.97,3537.82 ccw(c4917.58,3528.43) 4917.58,3541.71 ccw(c4917.58,3554.99) v1@4926.97,3545.6
  Bottom Layer w4: v1(1798.52,2934.04) 1840.19,2975.71 1840.19,3025.04 1856.86,3041.71 2257.52,3041.71 v1(2390.86,3175.04) ; v1@1798.52,2939.54 ccw(c1798.52,2952.82) 1807.91,2943.43 ccw(c1817.3,2934.04) v1@1804.02,2934.04 ; v1@1798.52,2943.54 ccw(c1798.52,2966.48) 1814.74,2950.26 ccw(c1830.96,2934.04) v1@1808.02,2934.04 ; v1@2381.36,3175.04 cw(c2358.42,3175.04) 2374.64,3158.82 cw(c2390.86,3142.61) v1@2390.86,3165.54 ; v1@2385.36,3175.04 cw(c2372.08,3175.04) 2381.47,3165.65 cw(c2390.86,3156.26) v1@2390.86,3169.54
PBIO.D12: EXTHDR1.26 U8.AE4 | length 4692
  Top Layer w4: EXTHDR1.26@1747.71,2910.03 ccw(c1734.06,2923.68) 1753.37,2923.68 ccw(c1772.68,2923.68) EXTHDR1.26@1759.03,2910.03 ; v1@1750.14,2984.99 cw(c1733.92,2968.77) 1756.86,2968.77 cw(c1779.79,2968.77) v1@1763.57,2984.99 ; v1@1752.97,2987.82 cw(c1743.58,2978.43) 1756.86,2978.43 cw(c1770.14,2978.43) v1@1760.75,2987.82 ; EXTHDR1.26@1753.37,2859.25 1753.37,2951.51 1756.86,2955 v1(1756.86,2991.71) ; v1(4973.52,3555.37) 4973.52,3570.37 5000.48,3597.33 5000.48,3660 5000.48,3670 5000.48,3717.53 ; 5000.48,3717.53 cw(c5010.63,3717.53) 5003.45,3724.71 ; 5000.48,3717.53 cw(c5010.63,3717.53) 5003.45,3724.71 ; 5003.45,3724.71 cw(c5015.98,3712.17) 5015.98,3729.9 ccw(c5015.98,3712.17) 5003.45,3724.71 ; 5003.45,3724.71 ccw(c4990.92,3737.24) 5008.64,3737.24 cw(c4990.92,3737.24) 5003.45,3724.71
  MidLayer2 w4: v1@1747.36,2991.71 ccw(c1724.42,2991.71) 1740.64,3007.93 ccw(c1756.86,3024.14) v1@1756.86,3001.21 ; v1@1751.36,2991.71 ccw(c1738.08,2991.71) 1747.47,3001.1 ccw(c1756.86,3010.49) v1@1756.86,2997.21 ; v1(1756.86,2991.71) 1715,3033.56 1676.7,3033.56 1568.17,2925.04 1556.86,2925.04 1547.52,2934.37 1547.52,2935 1527.92,2954.6 1525.65,2954.6 1515.4,2964.85 1515.4,3085.4 1530.37,3100.37 2207.19,3100.37 2223.52,3116.71 2617.56,3116.71 2625.9,3108.37 3151.51,3108.37 3209.84,3166.71 4265.19,3166.71 4341.86,3243.37 4390.19,3243.37 4405.19,3258.37 4577.19,3258.37 4656.86,3338.04 4742.86,3338.04 4756.86,3324.04 4805,3324.04 4814.19,3324.04 4819.54,3324.04 4923.52,3428.02 4923.52,3433.37 4923.52,3447.37 4987.19,3511.04 4987.19,3541.71 v1(4973.52,3555.37)
PBIO.D13: EXTHDR1.28 U8.AF3 | length 5285.8
  Top Layer w4: EXTHDR1.28@1716.22,2808.48 cw(c1702.56,2794.82) 1721.87,2794.82 cw(c1741.19,2794.82) EXTHDR1.28@1727.53,2808.48 ; EXTHDR1.28@1721.87,2859.25 1721.87,2750.36 v1(2013.86,2458.37) ; v1@2004.36,2458.37 ccw(c1981.42,2458.37) 1997.64,2474.59 ccw(c2013.86,2490.81) v1@2013.86,2467.87 ; v1@2008.36,2458.37 ccw(c1995.08,2458.37) 2004.47,2467.76 ccw(c2013.86,2477.15) v1@2013.86,2463.87 ; v1@4876.05,3529.9 ccw(c4866.94,3541.71) 4881.86,3541.71 ; v1(4881.86,3522.37) 4881.86,3541.71 ; v1@4887.66,3529.9 cw(c4896.78,3541.71) 4881.86,3541.71 ; U8.AF3@4971.31,3692.57 cw(c4958.51,3679.77) 4976.61,3679.77 cw(c4994.72,3679.77) U8.AF3@4981.92,3692.57 ; U8.AF3@4971.42,3692.68 cw(c4958.89,3680.15) 4976.61,3680.15 cw(c4994.34,3680.15) U8.AF3@4981.81,3692.68 ; U8.AF3@4976.61,3697.87 4976.61,3670 4976.61,3660 4976.61,3655.26 4976.61,3633.7 4982.69,3627.62 4982.69,3609.19 4948.21,3574.71 4914.86,3574.71 4907.26,3567.11 4881.86,3541.71
  MidLayer1 w4: v1@4876.14,2465.09 ccw(c4842.22,2499.01) 4890.19,2499.01 ; v1@4878.97,2462.26 ccw(c4851.88,2489.36) 4890.19,2489.36 ; v1@4881.8,2459.44 ccw(c4861.53,2479.7) 4890.19,2479.7 ; v1@4881.86,3512.87 cw(c4881.86,3489.94) 4898.07,3506.16 cw(c4914.29,3522.37) v1@4891.36,3522.37 ; v1@4881.86,3516.87 cw(c4881.86,3503.6) 4891.25,3512.99 cw(c4900.64,3522.37) v1@4887.36,3522.37 ; v1(4881.86,3522.37) 4899.52,3504.71 4899.52,3432.37 4948.52,3383.37 4948.52,3231 4915,3197.48 4915,3175 ; v1(4882.86,2458.37) 4890.19,2465.71 4890.19,2650.04 4915.19,2675.04 4915.19,3175 ; v1@4884.62,2456.61 ccw(c4871.19,2470.04) 4890.19,2470.04
  MidLayer2 w4: v1@2013.86,2448.87 cw(c2013.86,2425.94) 2030.07,2442.16 cw(c2046.29,2458.37) v1@2023.36,2458.37 ; v1@2013.86,2452.87 cw(c2013.86,2439.6) 2023.25,2448.99 cw(c2032.64,2458.37) v1@2019.36,2458.37 ; v1(2013.86,2458.37) 2080.86,2391.37 2417.32,2391.37 2450.65,2358.04 2734.35,2358.04 2742.81,2366.5 2777.19,2366.5 2785.65,2358.04 3093.04,2358.04 3126.37,2391.37 4688,2391.37 4755,2458.37 v1(4882.86,2458.37) ; v1@4876.14,2451.66 ccw(c4859.92,2435.44) 4859.92,2458.37 ccw(c4859.92,2481.31) v1@4876.14,2465.09 ; v1@4878.97,2454.49 ccw(c4869.58,2445.1) 4869.58,2458.37 ccw(c4869.58,2471.65) v1@4878.97,2462.26
PBIO.D14: EXTHDR1.30 U8.AB1 | length 5798.3
  Top Layer w4: EXTHDR1.30@1686.52,2807.13 cw(c1675.32,2786.8) v1@1698.52,2786.8 ; EXTHDR1.30@1688.45,2810.63 cw(c1679.05,2793.57) v1@1698.52,2793.57 ; EXTHDR1.30@1690.38,2814.13 cw(c1682.78,2800.34) 1698.52,2800.34 ; EXTHDR1.30@1690.38,2859.25 1690.38,2813.15 1698.52,2805 v1(1698.52,2788.04) ; EXTHDR1.30@1693.08,2806.6 cw(c1694.68,2802.14) 1698.03,2805.49 cw(c1700.85,2808.31) EXTHDR1.30@1697.37,2810.24 ; v1@1693.56,2796.14 ccw(c1688.14,2805) 1698.52,2805 ccw(c1708.91,2805) v1@1703.49,2796.14 ; v1(2931.86,3039.37) 3099.37,3039.37 3181.86,3121.86 v1(3181.86,3283.37) ; v1@2935.75,3035.49 cw(c2945.14,3026.1) 2945.14,3039.37 cw(c2945.14,3052.65) v1@2935.75,3043.26 ; v1@2938.57,3032.66 cw(c2954.79,3016.44) 2954.79,3039.37 cw(c2954.79,3062.31) v1@2938.57,3046.09 ; v1@3175.14,3276.66 cw(c3158.92,3260.44) 3181.86,3260.44 cw(c3204.79,3260.44) v1@3188.57,3276.66 ; v1@3177.97,3279.49 cw(c3168.58,3270.1) 3181.86,3270.1 cw(c3195.14,3270.1) v1@3185.75,3279.49 ; v1@4707.81,3674.43 ccw(c4691.59,3690.64) 4714.52,3690.64 ccw(c4737.46,3690.64) v1@4721.24,3674.43 ; v1@4710.64,3671.6 ccw(c4701.25,3680.99) 4714.52,3680.99 ccw(c4727.8,3680.99) v1@4718.41,3671.6 ; v1(4714.52,3667.71) 4714.52,3704.6 4734.81,3724.88 4734.81,3740.19 4727.93,3747.07 4722.93,3747.07 4688.52,3781.48 4688.52,3810.9 4732.98,3855.35 4860,3855.35 4870,3855.35 U8.AB1@4897.87,3855.35 ; U8.AB1@4892.57,3850.05 ccw(c4879.77,3837.25) 4879.77,3855.35 ccw(c4879.77,3873.46) U8.AB1@4892.57,3860.66 ; U8.AB1@4892.68,3850.16 ccw(c4880.15,3837.63) 4880.15,3855.35 ccw(c4880.15,3873.08) U8.AB1@4892.68,3860.55
  MidLayer2 w4: v1@3940.19,3498.87 cw(c3940.19,3475.94) 3956.41,3492.16 cw(c3972.63,3508.37) v1@3949.69,3508.37 ; v1@3940.19,3502.87 cw(c3940.19,3489.6) 3949.58,3498.99 cw(c3958.97,3508.37) v1@3945.69,3508.37 ; v1(3940.19,3508.37) 4006.86,3441.71 4015.19,3441.71 4048.52,3408.37 4073.52,3408.37 4131.86,3466.71 4131.86,3516.71 4148.52,3533.37 4173.52,3533.37 4215.19,3575.04 4215.19,3708.37 4173.52,3750.04 4173.52,3758.37 4198.52,3783.37 4251.52,3783.37 4376.52,3658.37 4706.52,3658.37 v1@4715.19,3667.04
  Bottom Layer w4: v1(1698.52,2788.04) 1735,2824.52 1735,3020.04 1765,3050.04 2085,3050.04 2244,3209.04 2721.35,3209.04 2930.69,2999.71 3106.52,2999.71 3123.52,3016.71 3123.52,3048.37 3121.86,3050.04 3030,3050.04 3020.41,3040.45 2932.93,3040.45 v1(2931.86,3039.37) ; v1@1698.52,2793.54 ccw(c1698.52,2806.82) 1707.91,2797.43 ccw(c1717.3,2788.04) v1@1704.02,2788.04 ; v1@1698.52,2797.54 ccw(c1698.52,2820.48) 1714.74,2804.26 ccw(c1730.96,2788.04) v1@1708.02,2788.04 ; v1@2935.75,3035.49 cw(c2947.73,3023.5) 2947.73,3040.45 ; v1@2938.57,3032.66 cw(c2957.38,3013.85) 2957.38,3040.45 ; v1@2938.57,3046.09 ccw(c2952.2,3059.72) 2952.2,3040.45 ; v1(3181.86,3283.37) 3198.86,3300.37 3935.86,3300.37 3956.86,3321.37 3969.86,3321.37 3990.19,3341.71 3990.19,3458.37 v1(3940.19,3508.37) ; v1@3181.86,3288.87 ccw(c3181.86,3302.15) 3191.25,3292.76 ccw(c3200.64,3283.37) v1@3187.36,3283.37 ; v1@3181.86,3292.87 ccw(c3181.86,3315.81) 3198.07,3299.59 ccw(c3214.29,3283.37) v1@3191.36,3283.37 ; v1@3940.19,3498.87 cw(c3940.19,3475.94) 3956.41,3492.16 cw(c3972.63,3508.37) v1@3949.69,3508.37 ; v1@3940.19,3502.87 cw(c3940.19,3489.6) 3949.58,3498.99 cw(c3958.97,3508.37) v1@3945.69,3508.37
PBIO.D15: EXTHDR1.32 U8.AA7 | length 4675
  Top Layer w4: EXTHDR1.32@1653.92,2910.65 ccw(c1649.13,2916.71) 1656.86,2916.71 ; EXTHDR1.32@1656.86,2883.37 1656.86,2916.71 ; EXTHDR1.32@1660.52,2912.2 cw(c1661.46,2916.71) 1656.86,2916.71 ; v1@1672.36,2941.71 cw(c1649.42,2941.71) 1665.64,2925.49 cw(c1681.86,2909.27) v1@1681.86,2932.21 ; v1@1676.36,2941.71 cw(c1663.08,2941.71) 1672.47,2932.32 cw(c1681.86,2922.93) v1@1681.86,2936.21 ; v1(1681.86,2941.71) 1656.86,2916.71 ; v3(5114.41,3875.04) U8.AA7@5134.09,3894.72 ; U8.AA7@5126.59,3894.72 cw(c5108.49,3894.72) 5121.29,3881.92 cw(c5134.09,3869.12) U8.AA7@5134.09,3887.22 ; U8.AA7@5126.75,3894.72 cw(c5109.03,3894.72) 5121.56,3882.19 cw(c5134.09,3869.66) U8.AA7@5134.09,3887.38 ; 5127.21,3887.84 cw(c5114.41,3900.65) 5114.41,3882.54 ccw(c5114.41,3900.65) 5127.21,3887.84 ; 5127.21,3887.84 ccw(c5140.02,3875.04) 5121.91,3875.04 cw(c5140.02,3875.04) 5127.21,3887.84
  MidLayer1 w4: v1(4956.86,3166.71) 4956.86,3175.04 4972.86,3191.04 ; v1@4958.33,3167.01 cw(c4972.9,3170.03) 4962.38,3180.56 ; v1@4962.24,3167.82 cw(c4981.58,3171.83) 4967.62,3185.8 ; v1@4966.16,3168.64 cw(c4990.26,3173.63) 4972.86,3191.04 ; 5090.55,3798.23 5090.55,3812.16 ; v3@5107.02,3873.74 cw(c5089.19,3870.59) 5104.02,3860.21 ; v3@5115.71,3867.65 ccw(c5118.86,3849.82) 5104.02,3860.21 ; 4972.86,3191.04 4972.86,3383.04 5040.19,3450.37 5040.19,3551.67 5052,3563.48 5052,3600.52 5061.43,3609.95 5079,3627.52 5090.55,3639.06 5090.55,3660 5090.55,3670 5090.55,3718.62 5090.55,3738.04 5090.55,3812.16 ; 5090.55,3812.16 5090.55,3835.41 cw(c5114.32,3835.41) 5096.94,3851.63 5104.02,3860.21
  MidLayer2 w4: v1(1681.86,2941.71) 1743.29,2941.71 1768.63,2916.37 1881.37,2916.37 1919.41,2954.41 1952.49,2954.41 1998.52,2908.37 2031.86,2908.37 2081.86,2958.37 3290.19,2958.37 3298.52,2966.71 4505.88,2966.71 4572.54,3033.37 4823.52,3033.37 v1(4956.86,3166.71) ; v1@1685.75,2937.82 cw(c1695.14,2928.43) 1695.14,2941.71 cw(c1695.14,2954.99) v1@1685.75,2945.6 ; v1@1688.57,2934.99 cw(c1704.79,2918.77) 1704.79,2941.71 cw(c1704.79,2964.64) v1@1688.57,2948.43 ; v1@4947.36,3166.71 cw(c4924.42,3166.71) 4940.64,3150.49 cw(c4956.86,3134.27) v1@4956.86,3157.21 ; v1@4951.36,3166.71 cw(c4938.08,3166.71) 4947.47,3157.32 cw(c4956.86,3147.93) v1@4956.86,3161.21
PBIO.D16: EXTHDR1.34 U8.Y5 | length 6037.2
  Top Layer w4: EXTHDR1.34@1621.73,2808.48 cw(c1608.07,2794.82) 1627.39,2794.82 cw(c1646.7,2794.82) EXTHDR1.34@1633.04,2808.48 ; EXTHDR1.34@1627.39,2859.25 1627.39,2721.18 v1(1756.86,2591.71) ; v1@1747.36,2591.71 ccw(c1724.42,2591.71) 1740.64,2607.93 ccw(c1756.86,2624.14) v1@1756.86,2601.21 ; v1@1751.36,2591.71 ccw(c1738.08,2591.71) 1747.47,2601.1 ccw(c1756.86,2610.49) v1@1756.86,2597.21 ; v3(5035.67,3914.41) U8.Y5@5055.35,3934.09 ; U8.Y5@5047.85,3934.09 cw(c5029.75,3934.09) 5042.55,3921.29 cw(c5055.35,3908.49) U8.Y5@5055.35,3926.59 ; U8.Y5@5048.01,3934.09 cw(c5030.29,3934.09) 5042.82,3921.56 cw(c5055.35,3909.03) U8.Y5@5055.35,3926.75 ; 5048.47,3927.21 cw(c5035.67,3940.02) 5035.67,3921.91 ccw(c5035.67,3940.02) 5048.47,3927.21 ; 5048.47,3927.21 ccw(c5061.28,3914.41) 5043.17,3914.41 cw(c5061.28,3914.41) 5048.47,3927.21
  MidLayer1 w4: v1@3891.81,2873.43 ccw(c3875.59,2889.64) 3898.52,2889.64 ccw(c3921.46,2889.64) v1@3905.24,2873.43 ; v1@3894.64,2870.6 ccw(c3885.25,2879.99) 3898.52,2879.99 ccw(c3911.8,2879.99) v1@3902.41,2870.6 ; v1(3898.52,2866.71) 3898.52,2944.08 4272.52,3318.08 4272.52,3983.2 4356.03,4066.71 4515.19,4066.71 4531.86,4050.04 4531.86,4041.71 4498.52,4008.37 4498.52,3983.37 4515.19,3966.71 4647.52,3966.71 4669.52,3944.71 4669.52,3670.71 4681.86,3658.37 4681.86,3624.04 4697.52,3608.37 4723.52,3608.37 4773.52,3658.37 4773.52,3700.04 4790.19,3716.71 4790.19,3751.71 4783.52,3758.37 4783.52,3888.52 4793.9,3898.9 4860,3898.9 4870,3898.9 4918.62,3898.9 5012.16,3898.9 ccw(c5012.16,3912.95) 5022.09,3903.02 ; v3@5028.2,3915.06 cw(c5010.16,3916.64) 5021.8,3902.77 cw(c5033.44,3888.9) v3@5035.02,3906.94
  Bottom Layer w4: v1@1750.14,2598.43 ccw(c1733.92,2614.64) 1756.86,2614.64 ccw(c1779.79,2614.64) v1@1763.57,2598.43 ; v1@1752.97,2595.6 ccw(c1743.58,2604.99) 1756.86,2604.99 ccw(c1770.14,2604.99) v1@1760.75,2595.6 ; v1(1756.86,2591.71) 1756.86,2646.86 1785.71,2675.71 2164.69,2675.71 2206.69,2633.71 2991.29,2633.71 3008.29,2616.71 3023.52,2616.71 3031.86,2625.04 3198.52,2625.04 3206.86,2616.71 3248.29,2616.71 3255.19,2623.61 3255.19,2635.04 3248.52,2641.71 3248.52,2677.04 3256.86,2685.37 3288.52,2685.37 3294.19,2679.71 3319.86,2679.71 3327.68,2687.53 3355,2714.85 3355,2855 3426.37,2926.37 3838.86,2926.37 v1(3898.52,2866.71) ; v1@3889.02,2866.71 ccw(c3866.09,2866.71) 3882.31,2882.93 ccw(c3898.52,2899.14) v1@3898.52,2876.21 ; v1@3893.02,2866.71 ccw(c3879.75,2866.71) 3889.14,2876.1 ccw(c3898.52,2885.49) v1@3898.52,2872.21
